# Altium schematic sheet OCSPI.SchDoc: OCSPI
size A4; CompanyName: STMicroelectronics; Organization: Microcontrollers Division; DocumentNumber: 8; SheetNumber: 9; SheetTotal: 19
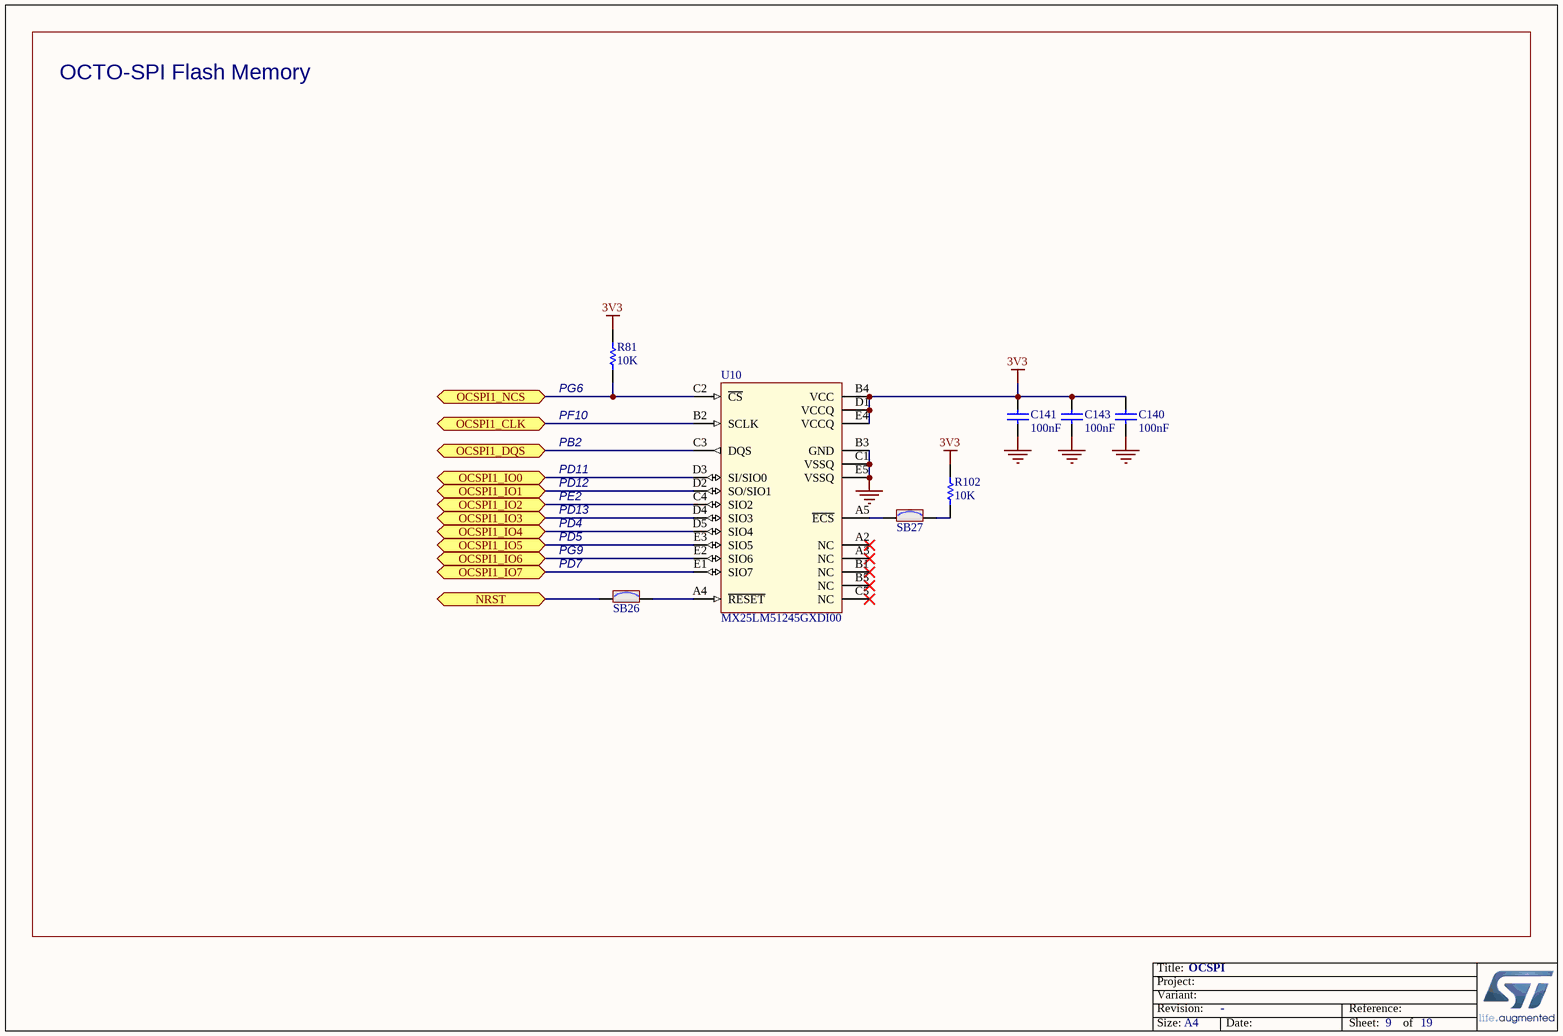
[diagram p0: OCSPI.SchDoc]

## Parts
C140  value 100nF  [C0402]  (hidden comment: Capacitor)
C141  value 100nF  [C0402]  (hidden comment: Capacitor)
C143  value 100nF  [C0402]  (hidden comment: Capacitor)
R81  value 10K  [R0402]  (hidden comment: Resistor)
R102  value 10K  [R0402]  (hidden comment: Resistor)
SB26  SB_ON  [SOLDER-BRIDGE_R0603-0R]  (value not drawn)
SB27  SB_ON  [SOLDER-BRIDGE_R0603-0R]  (value not drawn)
U10  MX25LM51245GXDI00  [ICC_BGA24_5X5-BALL-ARRAY_6X8_P1]

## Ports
NRST, OCSPI1_CLK (bidir), OCSPI1_DQS (bidir), OCSPI1_IO0 (bidir), OCSPI1_IO1 (bidir), OCSPI1_IO2 (bidir), OCSPI1_IO3 (bidir), OCSPI1_IO4 (bidir), OCSPI1_IO5 (bidir), OCSPI1_IO6 (bidir), OCSPI1_IO7 (bidir), OCSPI1_NCS (bidir)

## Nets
3V3: C140.2 C141.2 C143.2 R81.2 R102.2 U10.B4(VCC) U10.D1(VCCQ) U10.E4(VCCQ)
GND: C140.1 C141.1 C143.1 U10.B3(GND) U10.C1(VSSQ) U10.E5(VSSQ)
NRST: SB26.1 ; port NRST
OCSPI1_CLK: U10.B2(SCLK) ; port OCSPI1_CLK
OCSPI1_DQS: U10.C3(DQS) ; port OCSPI1_DQS
OCSPI1_IO0: U10.D3(SI/SIO0) ; port OCSPI1_IO0
OCSPI1_IO1: U10.D2(SO/SIO1) ; port OCSPI1_IO1
OCSPI1_IO2: U10.C4(SIO2) ; port OCSPI1_IO2
OCSPI1_IO3: U10.D4(SIO3) ; port OCSPI1_IO3
OCSPI1_IO4: U10.D5(SIO4) ; port OCSPI1_IO4
OCSPI1_IO5: U10.E3(SIO5) ; port OCSPI1_IO5
OCSPI1_IO6: U10.E2(SIO6) ; port OCSPI1_IO6
OCSPI1_IO7: U10.E1(SIO7) ; port OCSPI1_IO7
OCSPI1_NCS: R81.1 U10.C2(~{CS}) ; port OCSPI1_NCS
NetR102_1: R102.1 SB27.2
NetSB26_2: SB26.2 U10.A4(~{RESET})
NetSB27_1: SB27.1 U10.A5(~{ECS})

Not connected (* = marked no-connect by the designer): U10 A2(NC)* A3(NC)* B1(NC)* B5(NC)* C5(NC)*

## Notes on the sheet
- OCTO-SPI Flash Memory
- (near R81) PG6
- (near R81) PF10
- PB2
- PD11
- PD12
- PE2
- PD13
- PD4
- PD5
- PG9
- (near SB26) PD7

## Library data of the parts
C140 C141 C143 = MCD-00102: Capacitor, MLCC, 100nF, 16V, X7R, 10%, 0402, T=0,5mm; Manufacturer_Part_Number: CC0402KRX7R7BB104; Manufacturer: YAGEO; Alternate_Manufacturer_Part_Number: GCM155R71C104KA55D; Alternate_Manufacturer: MURATA; ECCN_US: EAR99; ECCN_EU: NEC; Provided_By: SUBCO
R81 R102 = MCD-00053: Resistor,10K,0402,1%,1/16W; Manufacturer_Part_Number: RC0402FR-0710KL; Manufacturer: YAGEO; ECCN_US: EAR99; ECCN_EU: NEC; Provided_By: SUBCO
SB26 SB27 = MCD-00071: Solder Bridge ON; Part_Type: Mechanical; Manufacturer_Part_Number: RC0603JR-070RL; Manufacturer: YAGEO; Provided_By: SUBCO
U10 = MCD-00246: Memory,Octo-SPI-NOR,512Mb,2048x16,133MHz,3V,DTR,BGA24, CMOS MXSMIO; Part_Type: IC; Manufacturer: MACRONIX; ECCN_US: 3A991.b.1.a; ECCN_EU: NEC; Provided_By: SUBCO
